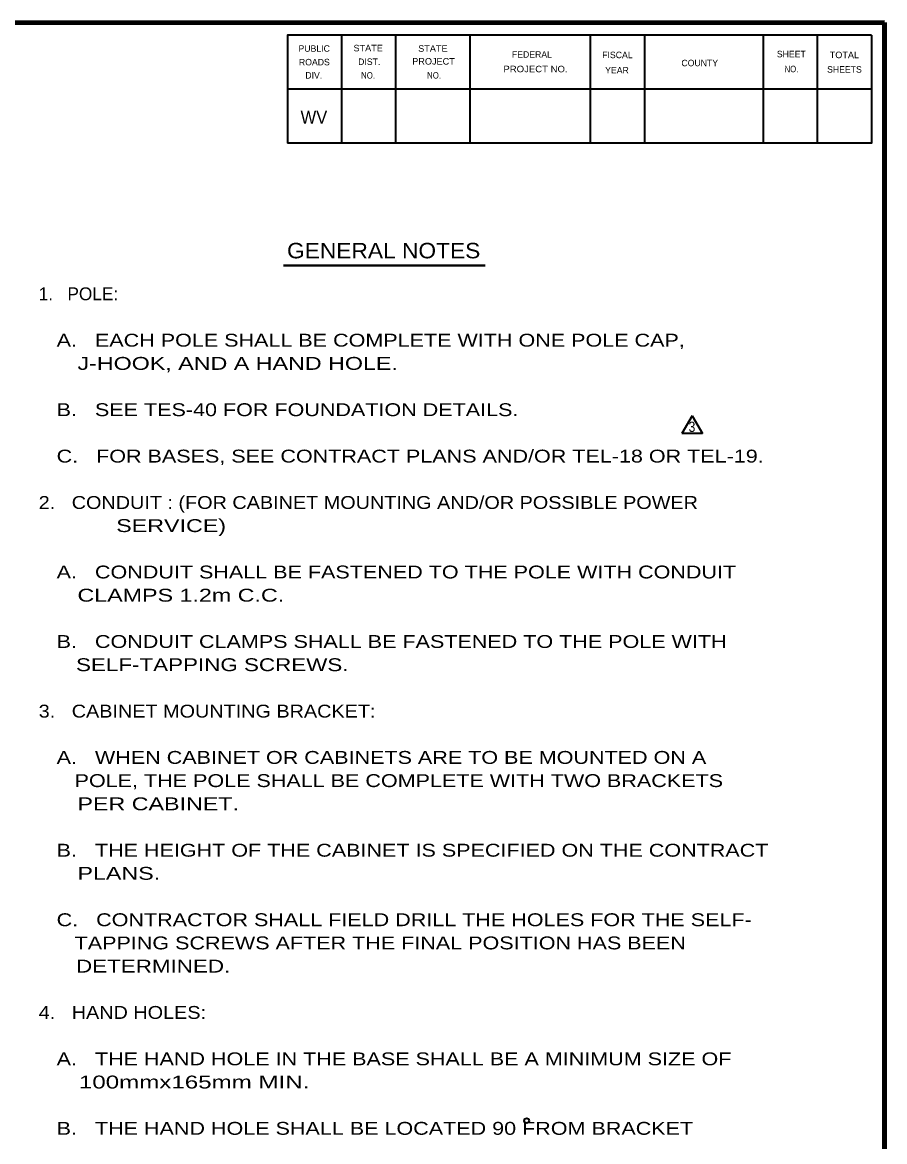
# Model space of a CAD drawing. Extents: x -23 to 690, y -228 to 443.
# Drawn here: x 515.3 to 684, y 218.8 to 437.8 of the extents above; entities that cross this region are included whole.
import ezdxf

# ---------------------------------------------------------------- set-up
doc = ezdxf.new("R2010")
doc.units = 0
doc.layers.add('1', color=7, linetype='Continuous', lineweight=35)
doc.layers.add('61', color=7, linetype='Continuous', lineweight=35)

msp = doc.modelspace()

# ---------------------------------------------------------------- linework, layer by layer
at = {"layer": '1', "lineweight": 158}
msp.add_line((684.026, -0.611), (684.026, 437.805), dxfattribs=at)
at = {"layer": '1', "lineweight": 13}
msp.add_line((684.026, -0.611), (684.026, 437.805), dxfattribs=at)
at = {"layer": '1', "lineweight": 40}
msp.add_line((566.411, 390.257), (605.851, 390.257), dxfattribs=at)
at = {"layer": '1'}
for p, q in [((646.385, 360.85), (644.385, 357.386)), ((646.385, 360.85), (648.385, 357.386)), ((648.385, 357.386), (644.385, 357.386))]:
    msp.add_line(p, q, dxfattribs=at)
at = {"layer": '1', "lineweight": 158}
msp.add_lwpolyline([(684.026, 437.805), (24.276, 437.722), (24.36, -0.611)], dxfattribs=at)
at = {"layer": '1'}
msp.add_circle((614.003, 222.892), 0.481, dxfattribs=at)
at = {"layer": '61'}
for p, q in [((577.776, 435.305), (577.776, 414.139)), ((588.36, 435.305), (588.36, 414.139)), ((602.86, 435.305), (602.86, 414.139)), ((626.443, 435.305), (626.443, 414.139)), ((637.026, 435.305), (637.026, 414.139)), ((660.276, 435.305), (660.276, 414.139)), ((670.86, 435.305), (670.86, 414.139)), ((681.443, 424.722), (567.193, 424.722))]:
    msp.add_line(p, q, dxfattribs=at)
for points in [[(681.443, 435.305), (567.193, 435.305), (567.193, 414.139)], [(681.443, 435.305), (681.443, 414.139), (567.193, 414.139)]]:
    msp.add_lwpolyline(points, dxfattribs=at)

# ---------------------------------------------------------------- texts
at = {"layer": '1'}
for s, height, width, p in [('WV', 2.54, 0.95, (569.776, 417.972)), ('GENERAL NOTES', 3.024, 1.1, (567.111, 391.637)), ('   A.   EACH POLE SHALL BE COMPLETE WITH ONE POLE CAP,', 2.52, 1.25, (518.531, 374.357)), ('      J-HOOK, AND A HAND HOLE.', 2.52, 1.35, (518.531, 369.817)), ('   B.   SEE TES-40 FOR FOUNDATION DETAILS.', 2.52, 1.25, (518.531, 360.757)), ('3', 2, 0.9, (645.66, 357.67)), ('   C.   FOR BASES, SEE CONTRACT PLANS AND/OR TEL-18 OR TEL-19.', 2.52, 1.25, (518.531, 351.677)), ('2.   CONDUIT : (FOR CABINET MOUNTING AND/OR POSSIBLE POWER', 2.52, 1.15, (518.531, 342.597)), ('            SERVICE)', 2.52, 1.35, (518.531, 338.077)), ('   A.   CONDUIT SHALL BE FASTENED TO THE POLE WITH CONDUIT', 2.52, 1.25, (518.531, 328.997)), ('      CLAMPS 1.2m C.C.', 2.52, 1.35, (518.531, 324.457)), ('   B.   CONDUIT CLAMPS SHALL BE FASTENED TO THE POLE WITH', 2.52, 1.25, (518.531, 315.397)), ('      SELF-TAPPING SCREWS.', 2.52, 1.3, (518.531, 310.857)), ('3.   CABINET MOUNTING BRACKET:', 2.52, 1.15, (518.531, 301.777)), ('   A.   WHEN CABINET OR CABINETS ARE TO BE MOUNTED ON A', 2.52, 1.25, (518.531, 292.717)), ('      POLE, THE POLE SHALL BE COMPLETE WITH TWO BRACKETS', 2.52, 1.25, (518.531, 288.177)), ('      PER CABINET.', 2.52, 1.35, (518.531, 283.637)), ('   B.   THE HEIGHT OF THE CABINET IS SPECIFIED ON THE CONTRACT', 2.52, 1.25, (518.531, 274.557)), ('      PLANS.', 2.52, 1.35, (518.531, 270.037)), ('   C.   CONTRACTOR SHALL FIELD DRILL THE HOLES FOR THE SELF-', 2.52, 1.25, (518.531, 260.957)), ('      TAPPING SCREWS AFTER THE FINAL POSITION HAS BEEN', 2.52, 1.25, (518.531, 256.417)), ('      DETERMINED.', 2.52, 1.3, (518.531, 251.877)), ('4.   HAND HOLES:', 2.52, 1.15, (518.531, 242.817)), ('   A.   THE HAND HOLE IN THE BASE SHALL BE A MINIMUM SIZE OF', 2.52, 1.25, (518.531, 233.737)), ('      100mmx165mm MIN.', 2.52, 1.4, (518.531, 229.197)), ('   B.   THE HAND HOLE SHALL BE LOCATED 90 FROM BRACKET', 2.52, 1.25, (518.531, 220.137))]:
    msp.add_text(s, height=height, dxfattribs=dict(at, width=width)).set_placement(p)
msp.add_text('1.   POLE:', height=2.52, dxfattribs=at).set_placement((518.531, 383.437))
at = {"layer": '61'}
for s, height, rotation, p in [('PUBLIC', 1.271, 0.033, (569.36, 432.055)), ('FEDERAL', 1.27, 0.007, (611.11, 430.889)), ('FISCAL', 1.271, 359.942, (628.776, 430.805)), ('SHEET', 1.271, 0.059, (662.943, 430.972)), ('ROADS', 1.27, 0.124, (569.443, 429.389)), ('DIST.', 1.27, 0.056, (581.026, 429.472)), ('COUNTY', 1.269, 0.069, (644.276, 429.222)), ('SHEETS', 1.269, 359.959, (672.776, 427.972)), ('DIV.', 1.27, 359.932, (570.693, 426.805)), ('YEAR', 1.27, 0.105, (629.36, 427.805))]:
    msp.add_text(s, height=height, rotation=rotation, dxfattribs=at).set_placement(p)
for s, height, rotation, width, p in [('STATE', 1.271, 0.059, 1.05, (580.11, 432.139)), ('STATE', 1.271, 0.059, 1.05, (592.776, 432.055)), ('TOTAL', 1.27, 359.926, 1.05, (673.276, 430.805)), ('PROJECT', 1.27, 359.908, 1.05, (591.61, 429.555)), ('PROJECT NO.', 1.27, 359.922, 1.1, (609.443, 428.055)), ('NO.', 1.27, 359.852, 0.9, (664.443, 428.055)), ('NO.', 1.27, 359.852, 0.9, (581.61, 426.805)), ('NO.', 1.271, 0.225, 0.9, (594.526, 426.805))]:
    msp.add_text(s, height=height, rotation=rotation, dxfattribs=dict(at, width=width)).set_placement(p)

doc.saveas('drawing.dxf')
